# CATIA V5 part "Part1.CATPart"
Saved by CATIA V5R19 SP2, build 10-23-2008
Part number: Part1
Bounding box of the stored display mesh (mm): x -82.488 to 170.958, y -72.716 to 33.473, z 7.5 to 27.5
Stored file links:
  C:\Documents and Settings\jurc\Plocha\Nový priečinok\Part1.CATPart
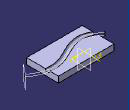
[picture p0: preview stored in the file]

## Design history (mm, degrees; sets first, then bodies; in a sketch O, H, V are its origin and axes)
Body1 (main body)
  Sketch1 on xy-plane, origin (0, 0, 0), H (1, 0, 0), V (0, 1, 0)
    line L1 (-65.7908, 33.4725) -> (119.2699, 33.4725)
    line L2 (119.2699, 33.4725) -> (119.2699, -72.7162)
    line L3 (119.2699, -72.7162) -> (-65.7908, -72.7162)
    line L4 (-65.7908, -72.7162) -> (-65.7908, 33.4725)
    horizontal: L1 H, L3 H
    vertical: L2 V, L4 V
  Pad1: profile Sketch1, direction (0, 0, 1), length 20
  Sketch2 on end face of Pad1, origin (0, 0, 20), H (1, 0, 0), V (0, 1, 0)
    spline S1 through (-82.4884, -14.85) (-10.7499, -39.9641) (60.2418, -10.6409) (170.9581, -28.2926)
  Plane1: type Normal, Curve Sketch2, RefPoint vertex of Sketch2
  Sketch3 on Plane1, origin (138.2146, -70.6279, 0), H (-0.6118, -0.791, 0), V (0, 0, 1)
    arc A1 centre (-53.5202, 20) radius 7.5 from (-61.0202, 20) to (-46.0202, 20) ccw
    point P1 (-61.0202, 20)
    line L1 (-61.0202, 20) -> (-46.0202, 20)
    reference projected point E1 (-53.5202, 20) from vertex of Sketch2
    reference projected point E2 (-53.5202, 20) from vertex of Sketch2
    radius A1 = 7.5
    distance E1 L1 = 0
    distance P1 E2 = 7.5
    horizontal: L1 H
  Slot1: profile Sketch3, centre curve Sketch2
  Translate1: Direction (0, 0, 1), Length 7.5, ToTransfor Slot1
  Plane2: stored without definition
  Sketch4 on end face of Pad1, origin (0, 0, 27.5), H (1, 0, 0), V (0, 1, 0)
    projected curve E1 from Sketch2.S1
